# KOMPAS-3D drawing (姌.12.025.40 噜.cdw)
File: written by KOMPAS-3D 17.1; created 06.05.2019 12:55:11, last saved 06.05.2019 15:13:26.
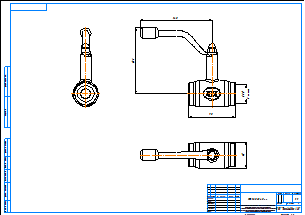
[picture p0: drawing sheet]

Sheet 1: A2, landscape

Title block, sheet 1: name: КШ.12.025.40 рр; material: Внимание! Данный продукт является объектом авторского права ООО «Торговый Дом АДЛ». / Запрещается изменение, копирование, распространение / (в том числе путем копирования на другие сайты и ресурсы в Интернете) / или любое иное использование информации и объектов без предварительного / согласия правообладателя (ООО «Торговый Дом АДЛ»).; scale: 1:1; sheets: 1; organisation: ООО "Торговый дом АДЛ"; sheet format: A2; stored path: C:\Users\tra\Desktop\2д чертежи\Шаровые краны БИВАЛ\КШ_Бивал_серия_11_12\KOMPAS_2D\КШ.12.025.40 рр.cdw

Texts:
  user
  RG 1
Dimensions and other numbers on the sheet: 90; 129; 2 места; 140; 51; 1:1; 1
